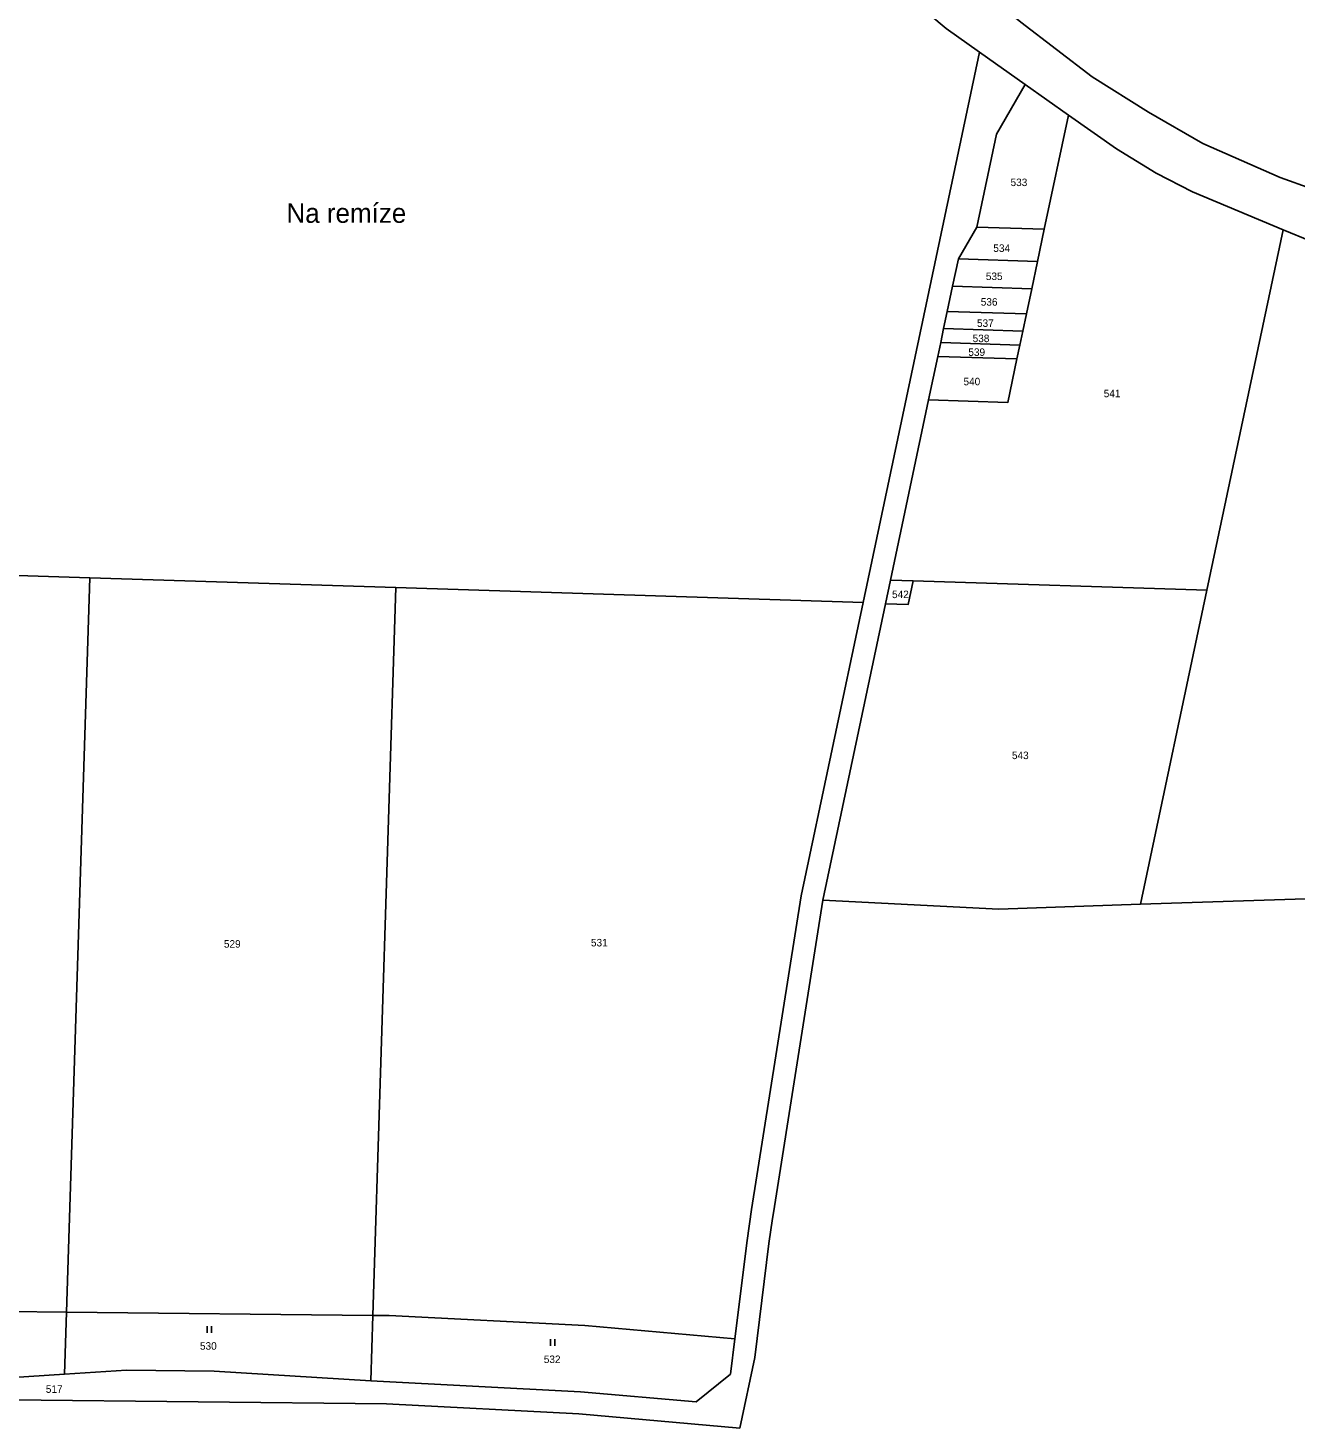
# Model space of a CAD drawing. Extents: x -769392 to -767038, y -1018329 to -1015269.
# Drawn here: x -768996.5 to -768709.3, y -1017910.4 to -1017593.3 of the extents above; entities that cross this region are included whole.
import ezdxf

# ---------------------------------------------------------------- set-up
doc = ezdxf.new("R2010")
doc.units = 0
doc.header["$LTSCALE"] = 0.68
for name, color, linetype, lineweight in [('1', 7, 'Continuous', 25), ('3', 7, 'Continuous', 25), ('7', 7, 'Continuous', 13)]:
    doc.layers.add(name, color=color, linetype=linetype, lineweight=lineweight)
doc.layers.add('2', color=7, linetype='Continuous')

msp = doc.modelspace()

# ---------------------------------------------------------------- linework, layer by layer
at = {"layer": '1'}
for p, q in [((-768807.34, -1017723.46), (-768781, -1017598.79)), ((-768781, -1017598.79), (-768770.64, -1017606.15)), ((-768770.64, -1017606.15), (-768760.86, -1017613.07)), ((-768766.32, -1017638.91), (-768760.86, -1017613.07)), ((-768785.78, -1017645.62), (-768781.61, -1017638.43)), ((-768781.61, -1017638.43), (-768766.32, -1017638.91)), ((-768767.85, -1017646.19), (-768766.32, -1017638.91)), ((-768729.48, -1017720.69), (-768712.23, -1017639.04)), ((-768712.23, -1017639.04), (-768705.98, -1017641.65)), ((-768785.78, -1017645.62), (-768787.09, -1017651.82)), ((-768767.85, -1017646.19), (-768785.78, -1017645.62)), ((-768769.17, -1017652.39), (-768767.85, -1017646.19)), ((-768787.09, -1017651.82), (-768788.3, -1017657.53)), ((-768769.17, -1017652.39), (-768787.09, -1017651.82)), ((-768770.37, -1017658.1), (-768769.17, -1017652.39)), ((-768788.3, -1017657.53), (-768789.12, -1017661.41)), ((-768788.3, -1017657.53), (-768770.37, -1017658.1)), ((-768771.19, -1017661.98), (-768770.37, -1017658.1)), ((-768789.12, -1017661.41), (-768789.78, -1017664.57)), ((-768771.19, -1017661.98), (-768789.12, -1017661.41)), ((-768771.86, -1017665.14), (-768771.19, -1017661.98)), ((-768789.78, -1017664.57), (-768790.45, -1017667.73)), ((-768789.78, -1017664.57), (-768771.86, -1017665.14)), ((-768772.53, -1017668.3), (-768771.86, -1017665.14)), ((-768790.45, -1017667.73), (-768792.54, -1017677.59)), ((-768772.53, -1017668.3), (-768790.45, -1017667.73)), ((-768792.54, -1017677.59), (-768801.16, -1017718.41)), ((-769023.57, -1017716.59), (-768982.47, -1017717.89)), ((-768982.47, -1017717.89), (-768987.76, -1017884.18)), ((-768982.47, -1017717.89), (-768913.16, -1017720.1)), ((-768801.16, -1017718.41), (-768802.29, -1017723.78)), ((-768801.16, -1017718.41), (-768796.04, -1017718.58)), ((-768796.04, -1017718.58), (-768729.48, -1017720.69)), ((-768918.4, -1017884.94), (-768913.16, -1017720.1)), ((-768913.16, -1017720.1), (-768807.34, -1017723.46)), ((-768744.51, -1017791.83), (-768729.48, -1017720.69)), ((-768802.29, -1017723.78), (-768816.46, -1017790.85)), ((-768816.46, -1017790.85), (-768827.67, -1017861.7)), ((-768776.65, -1017792.9), (-768816.46, -1017790.85)), ((-768744.51, -1017791.83), (-768776.65, -1017792.9)), ((-768704.84, -1017790.52), (-768744.51, -1017791.83)), ((-768827.67, -1017861.7), (-768827.86, -1017862.99)), ((-768827.86, -1017862.99), (-768828.68, -1017868.62)), ((-768828.68, -1017868.62), (-768831.86, -1017894.46)), ((-768987.76, -1017884.18), (-768988.2, -1017898.24)), ((-768987.76, -1017884.18), (-768918.4, -1017884.94)), ((-768918.87, -1017899.74), (-768918.4, -1017884.94)), ((-768831.86, -1017894.46), (-768835.24, -1017910.45)), ((-768915.3, -1017904.97), (-769000.63, -1017904.04)), ((-768871.75, -1017907.21), (-768915.3, -1017904.97)), ((-768835.24, -1017910.45), (-768871.75, -1017907.21))]:
    msp.add_line(p, q, dxfattribs=at)
for points in [[(-768705.75, -1017629.73), (-768712.89, -1017627.18), (-768730.41, -1017619.46), (-768742.74, -1017612.43), (-768755.47, -1017604.38), (-768771.64, -1017591.98), (-768783.52, -1017582.39), (-768815.53, -1017554.55), (-768835.62, -1017536.41), (-768859.73, -1017515.3), (-768896.78, -1017482.26), (-768938.25, -1017445.59), (-768960.52, -1017424.21)], [(-768821.21, -1017565.9), (-768807.98, -1017577.14), (-768788.56, -1017593.42), (-768781, -1017598.79)], [(-768781.61, -1017638.43), (-768777.17, -1017617.41), (-768770.64, -1017606.15)], [(-768760.86, -1017613.07), (-768749.99, -1017620.71), (-768740.95, -1017626.23), (-768732.74, -1017630.46), (-768712.23, -1017639.04)], [(-768772.53, -1017668.3), (-768774.61, -1017678.16), (-768792.54, -1017677.59)], [(-768802.29, -1017723.78), (-768797.18, -1017723.95), (-768796.04, -1017718.58)], [(-768836.38, -1017890.27), (-768833.64, -1017867.95), (-768832.61, -1017860.95), (-768821.38, -1017789.94), (-768807.34, -1017723.46)], [(-768987.76, -1017884.18), (-769001.16, -1017884.03), (-769028.95, -1017885.82)], [(-768918.4, -1017884.94), (-768914.68, -1017884.98), (-768870.35, -1017887.26), (-768836.38, -1017890.27)], [(-768918.87, -1017899.74), (-768871.4, -1017902.22), (-768845.19, -1017904.55), (-768837.36, -1017898.22), (-768836.38, -1017890.27)], [(-768918.87, -1017899.74), (-768954.36, -1017897.55), (-768974.16, -1017897.34), (-768988.2, -1017898.24)], [(-768988.2, -1017898.24), (-769000.95, -1017899.05), (-769029.43, -1017900.88)]]:
    msp.add_lwpolyline(points, dxfattribs=at)
at = {"layer": '3'}
for p, q in [((-768955.941, -1017888.88), (-768955.941, -1017887.38)), ((-768954.94, -1017888.88), (-768954.94, -1017887.38)), ((-768878.171, -1017891.84), (-768878.171, -1017890.34)), ((-768877.17, -1017891.84), (-768877.17, -1017890.34))]:
    msp.add_line(p, q, dxfattribs=at)

# ---------------------------------------------------------------- texts
at = {"layer": '2'}
for s, p in [('533', (-768773.96, -1017629.135)), ('534', (-768777.86, -1017644.045)), ('535', (-768779.56, -1017650.415)), ('536', (-768780.71, -1017656.215)), ('537', (-768781.56, -1017661.025)), ('538', (-768782.55, -1017664.485)), ('539', (-768783.52, -1017667.605)), ('540', (-768784.62, -1017674.255)), ('541', (-768752.86, -1017676.965)), ('542', (-768800.8, -1017722.465)), ('543', (-768773.65, -1017758.935)), ('529', (-768952.13, -1017801.645)), ('531', (-768869, -1017801.365)), ('530', (-768957.55, -1017892.715)), ('532', (-768879.68, -1017895.735)), ('517', (-768992.46, -1017902.485))]:
    msp.add_text(s, height=1.7, dxfattribs=at).set_placement(p)
at = {"layer": '7'}
msp.add_text('Na remíze', height=4.4, dxfattribs=at).set_placement((-768937.96, -1017637.46))

doc.saveas('drawing.dxf')
